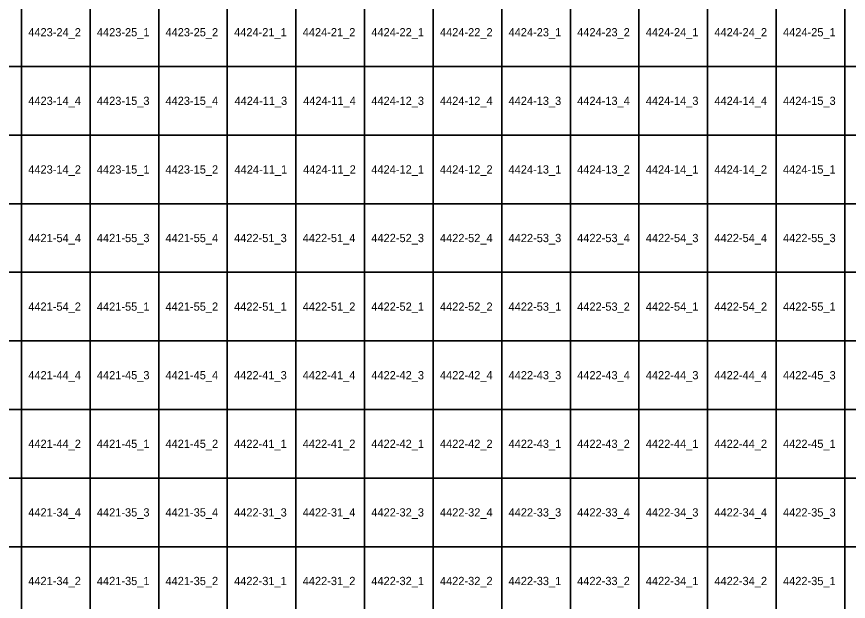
# Model space of a CAD drawing. Extents: x 312500 to 765000, y 172500 to 440000.
# Drawn here: x 667325 to 697629, y 310507 to 331819 of the extents above; entities that cross this region are included whole.
import ezdxf

# ---------------------------------------------------------------- set-up
doc = ezdxf.new("R2010")
doc.units = 0
doc.layers.add('Topo5_ramis_TKS2025', color=7, linetype='Continuous')
doc.layers.add('Topo5_ramis_TKS2025_Nr', color=7, linetype='Continuous')

msp = doc.modelspace()

# ---------------------------------------------------------------- linework, layer by layer
at = {"layer": 'Topo5_ramis_TKS2025'}
for points in [[(665000, 330000), (665000, 332500), (667500, 332500), (667500, 330000), (665000, 330000)], [(667500, 330000), (667500, 332500), (670000, 332500), (670000, 330000), (667500, 330000)], [(670000, 330000), (670000, 332500), (672500, 332500), (672500, 330000), (670000, 330000)], [(672500, 330000), (672500, 332500), (675000, 332500), (675000, 330000), (672500, 330000)], [(675000, 330000), (675000, 332500), (677500, 332500), (677500, 330000), (675000, 330000)], [(677500, 330000), (677500, 332500), (680000, 332500), (680000, 330000), (677500, 330000)], [(680000, 330000), (680000, 332500), (682500, 332500), (682500, 330000), (680000, 330000)], [(682500, 330000), (682500, 332500), (685000, 332500), (685000, 330000), (682500, 330000)], [(685000, 330000), (685000, 332500), (687500, 332500), (687500, 330000), (685000, 330000)], [(687500, 330000), (687500, 332500), (690000, 332500), (690000, 330000), (687500, 330000)], [(690000, 330000), (690000, 332500), (692500, 332500), (692500, 330000), (690000, 330000)], [(692500, 330000), (692500, 332500), (695000, 332500), (695000, 330000), (692500, 330000)], [(695000, 330000), (695000, 332500), (697500, 332500), (697500, 330000), (695000, 330000)], [(697500, 330000), (697500, 332500), (700000, 332500), (700000, 330000), (697500, 330000)], [(665000, 327500), (665000, 330000), (667500, 330000), (667500, 327500), (665000, 327500)], [(667500, 327500), (667500, 330000), (670000, 330000), (670000, 327500), (667500, 327500)], [(670000, 327500), (670000, 330000), (672500, 330000), (672500, 327500), (670000, 327500)], [(672500, 327500), (672500, 330000), (675000, 330000), (675000, 327500), (672500, 327500)], [(675000, 327500), (675000, 330000), (677500, 330000), (677500, 327500), (675000, 327500)], [(677500, 327500), (677500, 330000), (680000, 330000), (680000, 327500), (677500, 327500)], [(680000, 327500), (680000, 330000), (682500, 330000), (682500, 327500), (680000, 327500)], [(682500, 327500), (682500, 330000), (685000, 330000), (685000, 327500), (682500, 327500)], [(685000, 327500), (685000, 330000), (687500, 330000), (687500, 327500), (685000, 327500)], [(687500, 327500), (687500, 330000), (690000, 330000), (690000, 327500), (687500, 327500)], [(690000, 327500), (690000, 330000), (692500, 330000), (692500, 327500), (690000, 327500)], [(692500, 327500), (692500, 330000), (695000, 330000), (695000, 327500), (692500, 327500)], [(695000, 327500), (695000, 330000), (697500, 330000), (697500, 327500), (695000, 327500)], [(697500, 327500), (697500, 330000), (700000, 330000), (700000, 327500), (697500, 327500)], [(665000, 325000), (665000, 327500), (667500, 327500), (667500, 325000), (665000, 325000)], [(667500, 325000), (667500, 327500), (670000, 327500), (670000, 325000), (667500, 325000)], [(670000, 325000), (670000, 327500), (672500, 327500), (672500, 325000), (670000, 325000)], [(672500, 325000), (672500, 327500), (675000, 327500), (675000, 325000), (672500, 325000)], [(675000, 325000), (675000, 327500), (677500, 327500), (677500, 325000), (675000, 325000)], [(677500, 325000), (677500, 327500), (680000, 327500), (680000, 325000), (677500, 325000)], [(680000, 325000), (680000, 327500), (682500, 327500), (682500, 325000), (680000, 325000)], [(682500, 325000), (682500, 327500), (685000, 327500), (685000, 325000), (682500, 325000)], [(685000, 325000), (685000, 327500), (687500, 327500), (687500, 325000), (685000, 325000)], [(687500, 325000), (687500, 327500), (690000, 327500), (690000, 325000), (687500, 325000)], [(690000, 325000), (690000, 327500), (692500, 327500), (692500, 325000), (690000, 325000)], [(692500, 325000), (692500, 327500), (695000, 327500), (695000, 325000), (692500, 325000)], [(695000, 325000), (695000, 327500), (697500, 327500), (697500, 325000), (695000, 325000)], [(697500, 325000), (697500, 327500), (700000, 327500), (700000, 325000), (697500, 325000)], [(665000, 322500), (665000, 325000), (667500, 325000), (667500, 322500), (665000, 322500)], [(667500, 322500), (667500, 325000), (670000, 325000), (670000, 322500), (667500, 322500)], [(670000, 322500), (670000, 325000), (672500, 325000), (672500, 322500), (670000, 322500)], [(672500, 322500), (672500, 325000), (675000, 325000), (675000, 322500), (672500, 322500)], [(675000, 322500), (675000, 325000), (677500, 325000), (677500, 322500), (675000, 322500)], [(677500, 322500), (677500, 325000), (680000, 325000), (680000, 322500), (677500, 322500)], [(680000, 322500), (680000, 325000), (682500, 325000), (682500, 322500), (680000, 322500)], [(682500, 322500), (682500, 325000), (685000, 325000), (685000, 322500), (682500, 322500)], [(685000, 322500), (685000, 325000), (687500, 325000), (687500, 322500), (685000, 322500)], [(687500, 322500), (687500, 325000), (690000, 325000), (690000, 322500), (687500, 322500)], [(690000, 322500), (690000, 325000), (692500, 325000), (692500, 322500), (690000, 322500)], [(692500, 322500), (692500, 325000), (695000, 325000), (695000, 322500), (692500, 322500)], [(695000, 322500), (695000, 325000), (697500, 325000), (697500, 322500), (695000, 322500)], [(697500, 322500), (697500, 325000), (700000, 325000), (700000, 322500), (697500, 322500)], [(665000, 320000), (665000, 322500), (667500, 322500), (667500, 320000), (665000, 320000)], [(667500, 320000), (667500, 322500), (670000, 322500), (670000, 320000), (667500, 320000)], [(670000, 320000), (670000, 322500), (672500, 322500), (672500, 320000), (670000, 320000)], [(672500, 320000), (672500, 322500), (675000, 322500), (675000, 320000), (672500, 320000)], [(675000, 320000), (675000, 322500), (677500, 322500), (677500, 320000), (675000, 320000)], [(677500, 320000), (677500, 322500), (680000, 322500), (680000, 320000), (677500, 320000)], [(680000, 320000), (680000, 322500), (682500, 322500), (682500, 320000), (680000, 320000)], [(682500, 320000), (682500, 322500), (685000, 322500), (685000, 320000), (682500, 320000)], [(685000, 320000), (685000, 322500), (687500, 322500), (687500, 320000), (685000, 320000)], [(687500, 320000), (687500, 322500), (690000, 322500), (690000, 320000), (687500, 320000)], [(690000, 320000), (690000, 322500), (692500, 322500), (692500, 320000), (690000, 320000)], [(692500, 320000), (692500, 322500), (695000, 322500), (695000, 320000), (692500, 320000)], [(695000, 320000), (695000, 322500), (697500, 322500), (697500, 320000), (695000, 320000)], [(697500, 320000), (697500, 322500), (700000, 322500), (700000, 320000), (697500, 320000)], [(665000, 317500), (665000, 320000), (667500, 320000), (667500, 317500), (665000, 317500)], [(667500, 317500), (667500, 320000), (670000, 320000), (670000, 317500), (667500, 317500)], [(670000, 317500), (670000, 320000), (672500, 320000), (672500, 317500), (670000, 317500)], [(672500, 317500), (672500, 320000), (675000, 320000), (675000, 317500), (672500, 317500)], [(675000, 317500), (675000, 320000), (677500, 320000), (677500, 317500), (675000, 317500)], [(677500, 317500), (677500, 320000), (680000, 320000), (680000, 317500), (677500, 317500)], [(680000, 317500), (680000, 320000), (682500, 320000), (682500, 317500), (680000, 317500)], [(682500, 317500), (682500, 320000), (685000, 320000), (685000, 317500), (682500, 317500)], [(685000, 317500), (685000, 320000), (687500, 320000), (687500, 317500), (685000, 317500)], [(687500, 317500), (687500, 320000), (690000, 320000), (690000, 317500), (687500, 317500)], [(690000, 317500), (690000, 320000), (692500, 320000), (692500, 317500), (690000, 317500)], [(692500, 317500), (692500, 320000), (695000, 320000), (695000, 317500), (692500, 317500)], [(695000, 317500), (695000, 320000), (697500, 320000), (697500, 317500), (695000, 317500)], [(697500, 317500), (697500, 320000), (700000, 320000), (700000, 317500), (697500, 317500)], [(665000, 315000), (665000, 317500), (667500, 317500), (667500, 315000), (665000, 315000)], [(667500, 315000), (667500, 317500), (670000, 317500), (670000, 315000), (667500, 315000)], [(670000, 315000), (670000, 317500), (672500, 317500), (672500, 315000), (670000, 315000)], [(672500, 315000), (672500, 317500), (675000, 317500), (675000, 315000), (672500, 315000)], [(675000, 315000), (675000, 317500), (677500, 317500), (677500, 315000), (675000, 315000)], [(677500, 315000), (677500, 317500), (680000, 317500), (680000, 315000), (677500, 315000)], [(680000, 315000), (680000, 317500), (682500, 317500), (682500, 315000), (680000, 315000)], [(682500, 315000), (682500, 317500), (685000, 317500), (685000, 315000), (682500, 315000)], [(685000, 315000), (685000, 317500), (687500, 317500), (687500, 315000), (685000, 315000)], [(687500, 315000), (687500, 317500), (690000, 317500), (690000, 315000), (687500, 315000)], [(690000, 315000), (690000, 317500), (692500, 317500), (692500, 315000), (690000, 315000)], [(692500, 315000), (692500, 317500), (695000, 317500), (695000, 315000), (692500, 315000)], [(695000, 315000), (695000, 317500), (697500, 317500), (697500, 315000), (695000, 315000)], [(697500, 315000), (697500, 317500), (700000, 317500), (700000, 315000), (697500, 315000)], [(665000, 312500), (665000, 315000), (667500, 315000), (667500, 312500), (665000, 312500)], [(667500, 312500), (667500, 315000), (670000, 315000), (670000, 312500), (667500, 312500)], [(670000, 312500), (670000, 315000), (672500, 315000), (672500, 312500), (670000, 312500)], [(672500, 312500), (672500, 315000), (675000, 315000), (675000, 312500), (672500, 312500)], [(675000, 312500), (675000, 315000), (677500, 315000), (677500, 312500), (675000, 312500)], [(677500, 312500), (677500, 315000), (680000, 315000), (680000, 312500), (677500, 312500)], [(680000, 312500), (680000, 315000), (682500, 315000), (682500, 312500), (680000, 312500)], [(682500, 312500), (682500, 315000), (685000, 315000), (685000, 312500), (682500, 312500)], [(685000, 312500), (685000, 315000), (687500, 315000), (687500, 312500), (685000, 312500)], [(687500, 312500), (687500, 315000), (690000, 315000), (690000, 312500), (687500, 312500)], [(690000, 312500), (690000, 315000), (692500, 315000), (692500, 312500), (690000, 312500)], [(692500, 312500), (692500, 315000), (695000, 315000), (695000, 312500), (692500, 312500)], [(695000, 312500), (695000, 315000), (697500, 315000), (697500, 312500), (695000, 312500)], [(697500, 312500), (697500, 315000), (700000, 315000), (700000, 312500), (697500, 312500)], [(665000, 310000), (665000, 312500), (667500, 312500), (667500, 310000), (665000, 310000)], [(667500, 310000), (667500, 312500), (670000, 312500), (670000, 310000), (667500, 310000)], [(670000, 310000), (670000, 312500), (672500, 312500), (672500, 310000), (670000, 310000)], [(672500, 310000), (672500, 312500), (675000, 312500), (675000, 310000), (672500, 310000)], [(675000, 310000), (675000, 312500), (677500, 312500), (677500, 310000), (675000, 310000)], [(677500, 310000), (677500, 312500), (680000, 312500), (680000, 310000), (677500, 310000)], [(680000, 310000), (680000, 312500), (682500, 312500), (682500, 310000), (680000, 310000)], [(682500, 310000), (682500, 312500), (685000, 312500), (685000, 310000), (682500, 310000)], [(685000, 310000), (685000, 312500), (687500, 312500), (687500, 310000), (685000, 310000)], [(687500, 310000), (687500, 312500), (690000, 312500), (690000, 310000), (687500, 310000)], [(690000, 310000), (690000, 312500), (692500, 312500), (692500, 310000), (690000, 310000)], [(692500, 310000), (692500, 312500), (695000, 312500), (695000, 310000), (692500, 310000)], [(695000, 310000), (695000, 312500), (697500, 312500), (697500, 310000), (695000, 310000)], [(697500, 310000), (697500, 312500), (700000, 312500), (700000, 310000), (697500, 310000)]]:
    msp.add_lwpolyline(points, dxfattribs=at)

# ---------------------------------------------------------------- texts
at = {"layer": 'Topo5_ramis_TKS2025_Nr'}
for s, p in [('4423-24_2', (667748, 331100)), ('4423-25_1', (670248, 331100)), ('4423-25_2', (672748, 331100)), ('4424-21_1', (675248, 331100)), ('4424-21_2', (677748, 331100)), ('4424-22_1', (680248, 331100)), ('4424-22_2', (682748, 331100)), ('4424-23_1', (685248, 331100)), ('4424-23_2', (687748, 331100)), ('4424-24_1', (690248, 331100)), ('4424-24_2', (692748, 331100)), ('4424-25_1', (695248, 331100)), ('4423-14_4', (667748, 328600)), ('4423-15_3', (670248, 328600)), ('4423-15_4', (672748, 328600)), ('4424-11_3', (675264, 328600)), ('4424-11_4', (677764, 328600)), ('4424-12_3', (680248, 328600)), ('4424-12_4', (682748, 328600)), ('4424-13_3', (685248, 328600)), ('4424-13_4', (687748, 328600)), ('4424-14_3', (690248, 328600)), ('4424-14_4', (692748, 328600)), ('4424-15_3', (695248, 328600)), ('4423-14_2', (667748, 326100)), ('4423-15_1', (670248, 326100)), ('4423-15_2', (672748, 326100)), ('4424-11_1', (675264, 326100)), ('4424-11_2', (677764, 326100)), ('4424-12_1', (680248, 326100)), ('4424-12_2', (682748, 326100)), ('4424-13_1', (685248, 326100)), ('4424-13_2', (687748, 326100)), ('4424-14_1', (690248, 326100)), ('4424-14_2', (692748, 326100)), ('4424-15_1', (695248, 326100)), ('4421-54_4', (667748, 323600)), ('4421-55_3', (670248, 323600)), ('4421-55_4', (672748, 323600)), ('4422-51_3', (675248, 323600)), ('4422-51_4', (677748, 323600)), ('4422-52_3', (680248, 323600)), ('4422-52_4', (682748, 323600)), ('4422-53_3', (685248, 323600)), ('4422-53_4', (687748, 323600)), ('4422-54_3', (690248, 323600)), ('4422-54_4', (692748, 323600)), ('4422-55_3', (695248, 323600)), ('4421-54_2', (667748, 321100)), ('4421-55_1', (670248, 321100)), ('4421-55_2', (672748, 321100)), ('4422-51_1', (675248, 321100)), ('4422-51_2', (677748, 321100)), ('4422-52_1', (680248, 321100)), ('4422-52_2', (682748, 321100)), ('4422-53_1', (685248, 321100)), ('4422-53_2', (687748, 321100)), ('4422-54_1', (690248, 321100)), ('4422-54_2', (692748, 321100)), ('4422-55_1', (695248, 321100)), ('4421-44_4', (667748, 318600)), ('4421-45_3', (670248, 318600)), ('4421-45_4', (672748, 318600)), ('4422-41_3', (675248, 318600)), ('4422-41_4', (677748, 318600)), ('4422-42_3', (680248, 318600)), ('4422-42_4', (682748, 318600)), ('4422-43_3', (685248, 318600)), ('4422-43_4', (687748, 318600)), ('4422-44_3', (690248, 318600)), ('4422-44_4', (692748, 318600)), ('4422-45_3', (695248, 318600)), ('4421-44_2', (667748, 316100)), ('4421-45_1', (670248, 316100)), ('4421-45_2', (672748, 316100)), ('4422-41_1', (675248, 316100)), ('4422-41_2', (677748, 316100)), ('4422-42_1', (680248, 316100)), ('4422-42_2', (682748, 316100)), ('4422-43_1', (685248, 316100)), ('4422-43_2', (687748, 316100)), ('4422-44_1', (690248, 316100)), ('4422-44_2', (692748, 316100)), ('4422-45_1', (695248, 316100)), ('4421-34_4', (667748, 313600)), ('4421-35_3', (670248, 313600)), ('4421-35_4', (672748, 313600)), ('4422-31_3', (675248, 313600)), ('4422-31_4', (677748, 313600)), ('4422-32_3', (680248, 313600)), ('4422-32_4', (682748, 313600)), ('4422-33_3', (685248, 313600)), ('4422-33_4', (687748, 313600)), ('4422-34_3', (690248, 313600)), ('4422-34_4', (692748, 313600)), ('4422-35_3', (695248, 313600)), ('4421-34_2', (667748, 311100)), ('4421-35_1', (670248, 311100)), ('4421-35_2', (672748, 311100)), ('4422-31_1', (675248, 311100)), ('4422-31_2', (677748, 311100)), ('4422-32_1', (680248, 311100)), ('4422-32_2', (682748, 311100)), ('4422-33_1', (685248, 311100)), ('4422-33_2', (687748, 311100)), ('4422-34_1', (690248, 311100)), ('4422-34_2', (692748, 311100)), ('4422-35_1', (695248, 311100))]:
    msp.add_text(s, height=300, dxfattribs=at).set_placement(p)

doc.saveas('drawing.dxf')
